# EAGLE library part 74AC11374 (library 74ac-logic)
Octal D-type edge triggered FLIP FLOP, 3-state
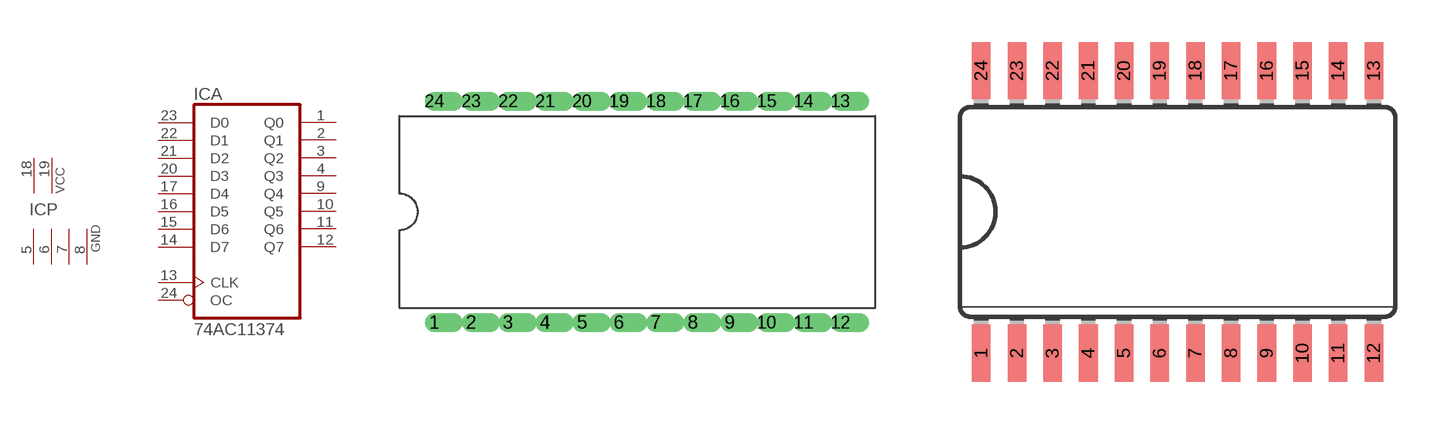
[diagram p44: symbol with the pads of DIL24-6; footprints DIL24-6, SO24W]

Designator prefix IC; gates A=7411374 P=2PWR4GND

## 74AC11374  [DIL24-6]
1  A:Q0  hiz
2  A:Q1  hiz
3  A:Q2  hiz
4  A:Q3  hiz
5  P:GND  pwr
6  P:GND  pwr
7  P:GND  pwr
8  P:GND  pwr
9  A:Q4  hiz
10  A:Q5  hiz
11  A:Q6  hiz
12  A:Q7  hiz
13  A:CLK  in
14  A:D7  in
15  A:D6  in
16  A:D5  in
17  A:D4  in
18  P:VCC  pwr
19  P:VCC  pwr
20  A:D3  in
21  A:D2  in
22  A:D1  in
23  A:D0  in
24  A:OC  in

## 74AC11374D  [SO24W]
Pads as for DIL24-6

## Footprint DIL24-6 (pad centres in mm)
Dual In Line 0.6 inch
drill 0.813 offset: 1 -13.97,-7.62; 2 -11.43,-7.62; 3 -8.89,-7.62; 4 -6.35,-7.62; 5 -3.81,-7.62; 6 -1.27,-7.62; 7 1.27,-7.62; 8 3.81,-7.62; 9 6.35,-7.62; 10 8.89,-7.62; 11 11.43,-7.62; 12 13.97,-7.62; 13 13.97,7.62; 14 11.43,7.62; 15 8.89,7.62; 16 6.35,7.62; 17 3.81,7.62; 18 1.27,7.62; 19 -1.27,7.62; 20 -3.81,7.62; 21 -6.35,7.62; 22 -8.89,7.62; 23 -11.43,7.62; 24 -13.97,7.62

## Footprint SO24W (pad centres in mm)
Wide Small Outline package 300 mil
smd 0.66 x 2.032: 1 -6.985,-5.029; 2 -5.715,-5.029; 3 -4.445,-5.029; 4 -3.175,-5.029; 5 -1.905,-5.029; 6 -0.635,-5.029; 7 0.635,-5.029; 8 1.905,-5.029; 9 3.175,-5.029; 10 4.445,-5.029; 11 5.715,-5.029; 12 6.985,-5.029; 13 6.985,5.029; 14 5.715,5.029; 15 4.445,5.029; 16 3.175,5.029; 17 1.905,5.029; 18 0.635,5.029; 19 -0.635,5.029; 20 -1.905,5.029; 21 -3.175,5.029; 22 -4.445,5.029; 23 -5.715,5.029; 24 -6.985,5.029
